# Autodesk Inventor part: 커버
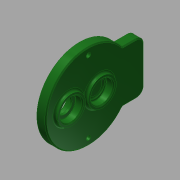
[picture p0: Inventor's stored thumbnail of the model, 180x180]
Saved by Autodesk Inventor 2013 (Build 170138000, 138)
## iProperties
Created: 2016-02
Part Number: 커버
Material: 알루미늄 6061
Document SubType Name: Modeling
Designer: mduedu
Density: 2.71 g/cm^3
Mass: 157.248 g
Surface Area: 178.476 cm^2
Volume: 58.0249 cm^3
Author: mduedu
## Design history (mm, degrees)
sketch "스케치1"
  geometry: C1 r 43 at (0, 0); 1 further point
  constraints: 1 centre point, 1 coincident
  dimensions: "d0" = 86 diameter of C1
extrude "돌출1" new body sketch "스케치1" distance "d1" = 9; taper "d2" = 0 deg
sketch "스케치2"
  geometry: C1 r 14 at (0, 11); 1 further point
  constraints: 1 centre point, 1 vertical alignment
  dimensions: "d3" = 28 diameter of C1; "d6" = 11 distance of C1.centre point (0, 0)
extrude "돌출2" join sketch "스케치2" distance "d7" = 3; taper "d8" = 0 deg
sketch "스케치3"
  geometry: C1 r 14 at (0, -20); 1 further point
  constraints: 1 centre point, 1 vertical alignment
  dimensions: "d9" = 28 diameter of C1; "d10" = 20 distance of C1.centre point (0, 0)
extrude "돌출3" join sketch "스케치3" distance "d11" = 3; taper "d12" = 0 deg
hole "구멍1" diameter "d15" = 22; stored, may be unused: countersink angle "d19" = 90 deg, drill point angle "d21" = 0 deg; dims "d13" = 10, "d14" = 10, "d16" = 6, "d17" = 4, "d18" = 2, "d20" = 7
hole "구멍2" diameter "d24" = 18; stored, may be unused: countersink angle "d28" = 90 deg, drill point angle "d30" = 0 deg; dims "d22" = 10, "d23" = 10, "d25" = 6, "d26" = 4, "d27" = 2, "d29" = 1
hole "구멍3" diameter "d33" = 22; stored, may be unused: countersink angle "d37" = 90 deg, drill point angle "d39" = 0 deg; dims "d34" = 6, "d35" = 4, "d36" = 2, "d38" = 7, "d73" = 10, "d74" = 10
sketch "스케치7"
  geometry: L1 (-26, 34.249)-(26, 34.249); L2 (26, 34.249)-(26, 56); L3 (26, 56)-(-26, 56); L4 (-26, 56)-(-26, 34.249); A1 r 43 centre (0, 0) between (-26, 34.249) and (26, 34.249) reference; 1 further point
  constraints: 8 end point, 2 parallel, 2 point on circle, 1 horizontal, 1 perpendicular
  dimensions: "d95" = 52 distance of L2.end L3.end; "d97" = 56 distance from line of L3 point (0, 0)
extrude "돌출5" join sketch "스케치7" stored distance "d98" = 10; taper "d99" = 0 deg
sketch "스케치4"
  geometry: C1 r 14 at (0, -20) reference; C2 r 18 at (0, -20); 1 further point
  constraints: 1 centre point, 1 coincident
  dimensions: "d40" = 36 diameter of C2
extrude "돌출4" join sketch "스케치4" distance "d41" = 4; taper "d42" = 0 deg
hole "구멍4" diameter "d45" = 22; stored, may be unused: countersink angle "d49" = 90 deg, drill point angle "d51" = 0 deg; dims "d43" = 10, "d44" = 10, "d46" = 6, "d47" = 4, "d48" = 2, "d50" = 7
hole "구멍5" diameter "d54" = 15; stored, may be unused: countersink angle "d58" = 90 deg, drill point angle "d60" = 0 deg; dims "d52" = 10, "d53" = 10, "d55" = 6, "d56" = 4, "d57" = 2, "d59" = 7
fillet "모깎기1" dims "d61" = 0.3
fillet "모깎기2" dims "d62" = 2
chamfer "모따기1" distance "d63" = 1; stored, may be unused: second distance "d64" = 2, angle "d65" = 45 deg
fillet "모깎기6" dims "d88" = 2
sketch "스케치5" dims "d67" = 72
  geometry: 4 further points
  constraints: 2 horizontal alignment, 1 coincident, 5 other
  dimensions: "d71" = 360 deg dimension on point (0, 0) point (-36, 0) (derived)
fillet "모깎기4" dims "d75" = 2
sketch "스케치6"
  geometry: 2 further points
hole "구멍6" sketch "스케치6" at (36, 0), (-36, 0) diameter "d76" = 4.5; stored, may be unused: countersink angle "d80" = 90 deg, drill point angle "d82" = 0 deg; dims "d77" = 6, "d78" = 8, "d79" = 4.6, "d81" = 8
fillet "모깎기7" dims "d100" = 8, "d101" = 2
chamfer "모따기2" distance "d90" = 1; stored, may be unused: second distance "d91" = 2, angle "d92" = 45 deg
node "솔리드1"
node "절단 모서리 투영1"
